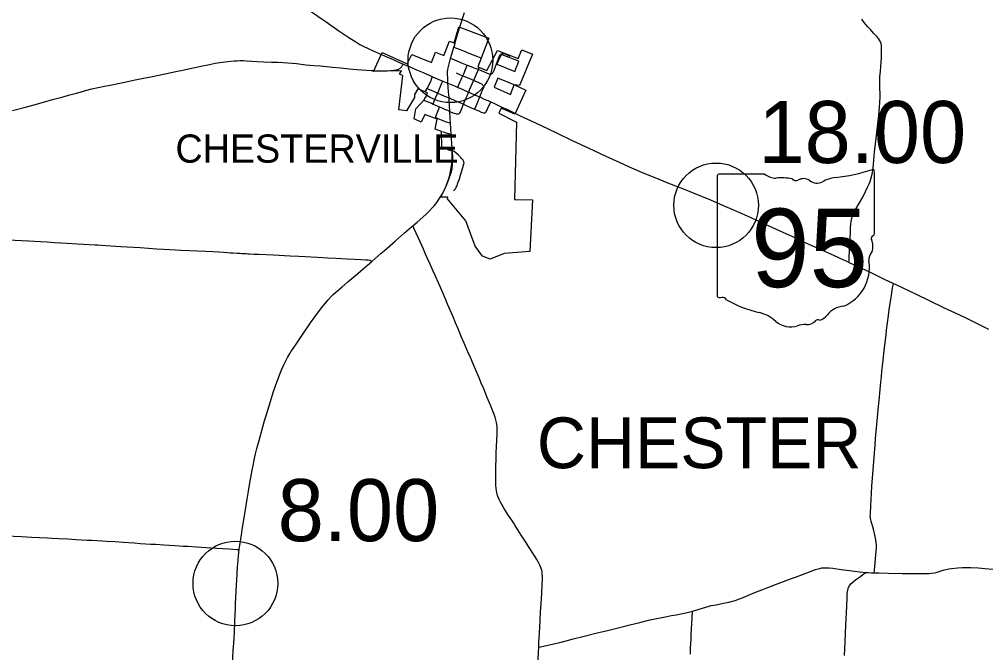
# Model space of a CAD drawing. Extents: x 1813937 to 1948437, y 826606 to 1022856.
# Drawn here: x 1909861 to 1926985, y 893308 to 904541 of the extents above; entities that cross this region are included whole.
import ezdxf

# ---------------------------------------------------------------- set-up
doc = ezdxf.new("R2010")
doc.units = 0
for name, color, linetype in [('Default', 7, 'Continuous'), ('GM_X_City_Street', 7, 'Continuous'), ('GM_X_Corporation', 7, 'Continuous'), ('GM_X_Corporation_Text', 7, 'Continuous'), ('GM_X_County_Road', 7, 'Continuous'), ('GM_X_State_Route', 7, 'Continuous'), ('GM_X_State_Shield', 7, 'Continuous'), ('GM_X_Township_Road', 7, 'Continuous'), ('GM_X_Township_Text', 7, 'Continuous')]:
    doc.layers.add(name, color=color, linetype=linetype)

msp = doc.modelspace()

# ---------------------------------------------------------------- linework, layer by layer
at = {"layer": 'Default'}
for centre in [(1917500, 903814), (1922208, 901242), (1913689, 894536)]:
    msp.add_circle(centre, 750, dxfattribs=at)
at = {"layer": 'GM_X_City_Street'}
for points in [[(1917561, 904044), (1917592, 904033), (1917670, 904005), (1917732, 903981), (1917824, 903943), (1917979, 903882), (1918010, 903871), (1918025, 903864), (1918039, 903855), (1918048, 903847)], [(1917504, 903846), (1917528, 903838), (1917570, 903821), (1917616, 903804), (1917710, 903765), (1917769, 903740), (1917797, 903728)], [(1917996, 903648), (1918029, 903638), (1918075, 903620), (1918151, 903586), (1918166, 903580), (1918182, 903574), (1918198, 903570), (1918214, 903569), (1918230, 903574), (1918243, 903584), (1918254, 903597), (1918261, 903612), (1918293, 903688), (1918318, 903750), (1918359, 903857), (1918371, 903888), (1918379, 903903), (1918388, 903916), (1918401, 903927), (1918416, 903933), (1918432, 903936), (1918449, 903934), (1918465, 903929), (1918495, 903916), (1918554, 903886)], [(1916149, 903631), (1916248, 903628), (1916348, 903629), (1916431, 903632), (1916496, 903637), (1916529, 903641), (1916545, 903643), (1916560, 903648), (1916575, 903653), (1916584, 903657), (1916591, 903661), (1916601, 903667), (1916612, 903676), (1916623, 903686), (1916632, 903696), (1916641, 903708), (1916648, 903721), (1916664, 903747)], [(1917720, 903539), (1917736, 903574), (1917767, 903648), (1917789, 903708), (1917797, 903728)], [(1917797, 903728), (1917830, 903715), (1917905, 903685), (1917965, 903660), (1917996, 903648)], [(1917914, 903457), (1917937, 903512), (1917975, 903599), (1917996, 903648)], [(1917996, 903648), (1917997, 903650), (1918012, 903687)], [(1917087, 903315), (1917109, 903354), (1917126, 903385), (1917140, 903413), (1917156, 903451), (1917166, 903478), (1917179, 903513), (1917183, 903523)], [(1917277, 903231), (1917305, 903305), (1917354, 903423), (1917364, 903446)], [(1917599, 903589), (1917660, 903564), (1917720, 903539)], [(1917631, 903333), (1917646, 903368), (1917703, 903501), (1917720, 903539)], [(1917720, 903539), (1917750, 903527), (1917855, 903483), (1917914, 903457)], [(1917824, 903249), (1917839, 903287), (1917910, 903447), (1917914, 903457)], [(1917914, 903457), (1917960, 903436), (1918020, 903409), (1918049, 903395), (1918063, 903386), (1918074, 903375), (1918083, 903362), (1918089, 903348), (1918091, 903337)], [(1917053, 903257), (1917087, 903315)], [(1917087, 903315), (1917113, 903303), (1917157, 903282), (1917277, 903231)], [(1918019, 903163), (1918065, 903275), (1918085, 903319), (1918091, 903337)], [(1917029, 903107), (1917032, 903105), (1917037, 903102), (1917044, 903099), (1917071, 903089), (1917162, 903052), (1917195, 903038)], [(1917195, 903038), (1917214, 903087), (1917262, 903199), (1917277, 903231)], [(1917277, 903231), (1917397, 903180), (1917475, 903146)], [(1917475, 903146), (1917590, 903095), (1917694, 903051), (1917731, 903035)], [(1917731, 903035), (1917769, 903125), (1917794, 903182), (1917816, 903230), (1917824, 903249)], [(1917929, 902945), (1917937, 902963), (1917955, 903006), (1917973, 903049), (1918016, 903156), (1918019, 903163)], [(1917195, 903038), (1917248, 903013), (1917305, 902988)], [(1917240, 902798), (1917239, 902802), (1917239, 902806), (1917240, 902811), (1917241, 902816), (1917282, 902922), (1917293, 902953), (1917305, 902988)], [(1917305, 902988), (1917334, 902976), (1917384, 902955), (1917426, 902938), (1917446, 902931), (1917461, 902925), (1917474, 902918), (1917490, 902905)], [(1917635, 902863), (1917643, 902866), (1917654, 902872), (1917665, 902882), (1917678, 902900), (1917690, 902931), (1917703, 902961), (1917731, 903035)], [(1917731, 903035), (1917766, 903018), (1917869, 902971), (1917929, 902945)], [(1917929, 902945), (1917956, 902933), (1918001, 902915), (1918046, 902896), (1918088, 902880), (1918094, 902880)], [(1918094, 902880), (1918111, 902883), (1918125, 902892), (1918135, 902904), (1918150, 902934), (1918170, 902980), (1918190, 903026), (1918204, 903053), (1918215, 903076)], [(1917240, 902798), (1917278, 902782), (1917338, 902757), (1917408, 902730), (1917463, 902712), (1917502, 902702)], [(1917490, 902905), (1917512, 902896), (1917559, 902879), (1917587, 902870), (1917602, 902866), (1917618, 902863), (1917626, 902862), (1917635, 902863)], [(1917359, 902551), (1917406, 902536), (1917424, 902530), (1917482, 902512), (1917516, 902502)], [(1917557, 901496), (1917587, 901533), (1917596, 901547), (1917604, 901561), (1917617, 901590), (1917628, 901621), (1917661, 901713), (1917681, 901774), (1917721, 901914), (1917738, 901977), (1917741, 901997), (1917739, 902011), (1917733, 902028), (1917725, 902042), (1917711, 902058), (1917698, 902075), (1917683, 902091), (1917661, 902115), (1917636, 902136), (1917599, 902168), (1917564, 902196), (1917555, 902202), (1917548, 902203), (1917533, 902203)]]:
    msp.add_lwpolyline(points, dxfattribs=at)
at = {"layer": 'GM_X_Corporation'}
for points in [[(1916721, 902918), (1916584, 902938), (1916654, 903543), (1916599, 903568), (1916631, 903626), (1916135, 903615), (1916288, 903951), (1916735, 903752), (1916814, 903917), (1917165, 903776), (1917235, 903959), (1917385, 903901), (1917482, 904153), (1917566, 904121), (1917650, 904410), (1918182, 904204), (1917985, 903695), (1918143, 903631), (1918332, 903987), (1918701, 903844), (1918764, 903997), (1918954, 903920), (1918724, 903365), (1918634, 903376), (1918838, 903282), (1918643, 902861), (1918401, 902967), (1918357, 902876), (1918671, 902719), (1918636, 901348), (1918654, 901348), (1918954, 901337), (1918907, 900420), (1918605, 900399), (1918453, 900386), (1918207, 900289), (1918069, 900338), (1917940, 900518), (1917772, 900966), (1917448, 901359), (1917457, 901388), (1917327, 901389), (1917348, 901423), (1917399, 901529), (1917464, 901686), (1917491, 901757), (1917517, 901838), (1917529, 901891), (1917543, 902040), (1917535, 902243), (1917506, 902241), (1917503, 902207), (1917349, 902273), (1917342, 902550), (1917230, 902590), (1917265, 902771), (1917048, 902854), (1916983, 902716), (1916860, 902776), (1916885, 902954), (1917033, 903113), (1917037, 903116), (1917058, 903162), (1917067, 903157), (1917096, 903235), (1916923, 903308), (1916866, 903208), (1916861, 903155)], [(1918324, 903745), (1918639, 903615), (1918714, 903796), (1918399, 903917)], [(1918276, 903338), (1918562, 903209), (1918627, 903378), (1918342, 903496)]]:
    msp.add_lwpolyline(points, close=True, dxfattribs=at)
at = {"layer": 'GM_X_County_Road'}
for points in [[(1912731, 903635), (1912752, 903640), (1913105, 903715), (1913233, 903742), (1913330, 903762), (1913411, 903775), (1913508, 903789), (1913606, 903799), (1913665, 903803)], [(1913665, 903803), (1913721, 903807), (1913770, 903809), (1913836, 903808), (1913881, 903807), (1913982, 903801), (1914073, 903794), (1914196, 903787), (1914332, 903781), (1914442, 903778), (1914539, 903775), (1914616, 903770), (1914695, 903763), (1914774, 903755), (1914855, 903744), (1914936, 903736), (1915082, 903723), (1915197, 903713), (1915409, 903693), (1915556, 903679), (1915703, 903665), (1915833, 903653), (1916013, 903641), (1916095, 903634), (1916149, 903631)], [(1909738, 902923), (1909944, 902978), (1910102, 903020), (1910292, 903073), (1910450, 903116), (1910640, 903168), (1910735, 903194), (1910877, 903233), (1910940, 903251), (1911035, 903277), (1911147, 903305), (1911259, 903330), (1911371, 903353), (1911500, 903379), (1911757, 903433), (1911885, 903459), (1912062, 903495), (1912223, 903528), (1912528, 903592), (1912656, 903620), (1912731, 903635)], [(1925011, 894725), (1925015, 894769), (1925026, 894899), (1925033, 894980), (1925045, 895111), (1925049, 895176), (1925049, 895225), (1925047, 895258), (1925040, 895307), (1925026, 895371), (1924994, 895498), (1924957, 895641), (1924946, 895688), (1924943, 895705), (1924940, 895737), (1924941, 895770), (1924950, 895917), (1924962, 896129), (1924970, 896259), (1924992, 896553), (1925002, 896700), (1925026, 896994), (1925035, 897109), (1925054, 897353), (1925079, 897614), (1925089, 897728), (1925101, 897842), (1925108, 897908), (1925127, 898103), (1925137, 898201), (1925147, 898299), (1925157, 898396), (1925168, 898494), (1925193, 898722), (1925202, 898803), (1925219, 898949), (1925230, 899030), (1925264, 899290), (1925277, 899388), (1925291, 899501), (1925313, 899647), (1925335, 899776), (1925343, 899825), (1925350, 899857)], [(1909620, 895383), (1909899, 895368), (1910079, 895359), (1910358, 895345), (1910439, 895341), (1910554, 895335), (1910718, 895326), (1910865, 895317), (1911062, 895306), (1911144, 895301), (1911242, 895295), (1911405, 895285), (1911552, 895278), (1911699, 895268), (1911896, 895256), (1912010, 895247), (1912190, 895235), (1912272, 895230), (1912419, 895221), (1912518, 895214), (1912616, 895208), (1912763, 895200), (1912845, 895196), (1913009, 895186), (1913254, 895170), (1913467, 895155), (1913581, 895147), (1913713, 895139), (1913758, 895138)], [(1921788, 894045), (1921909, 894079), (1922082, 894132), (1922120, 894142), (1922167, 894151), (1922210, 894159), (1922339, 894185), (1922436, 894205), (1922499, 894221), (1922546, 894235), (1922624, 894262), (1922685, 894285), (1922867, 894361), (1922973, 894405), (1923064, 894440), (1923125, 894464), (1923263, 894516), (1923356, 894551), (1923524, 894615), (1923616, 894650), (1923739, 894696), (1923893, 894753), (1923970, 894781), (1924017, 894796), (1924048, 894804), (1924081, 894810), (1924113, 894813), (1924163, 894815), (1924212, 894812), (1924277, 894805), (1924423, 894784), (1924570, 894765), (1924749, 894744), (1924863, 894733)], [(1924863, 894733), (1924904, 894730), (1924962, 894727), (1925011, 894725)], [(1925011, 894725), (1925093, 894722), (1925257, 894718), (1925503, 894713), (1925601, 894714), (1925831, 894710), (1925929, 894710), (1925979, 894713), (1926027, 894718), (1926076, 894727), (1926124, 894738), (1926250, 894775), (1926282, 894783), (1926330, 894793), (1926378, 894800), (1926493, 894812), (1926575, 894818), (1926657, 894820), (1926722, 894818), (1926853, 894812), (1926968, 894804), (1927115, 894792)], [(1919066, 893408), (1919150, 893423), (1919278, 893452), (1919310, 893460), (1919358, 893471), (1919438, 893491), (1919549, 893519), (1919613, 893536), (1919677, 893552), (1919868, 893601), (1920075, 893654), (1920282, 893704), (1920426, 893739), (1920681, 893801), (1920857, 893844), (1921009, 893882), (1921129, 893906), (1921306, 893944), (1921419, 893967), (1921500, 893980), (1921613, 894003), (1921674, 894017), (1921788, 894045)], [(1919051, 893107), (1919054, 893152), (1919057, 893206), (1919066, 893408)]]:
    msp.add_lwpolyline(points, dxfattribs=at)
at = {"layer": 'GM_X_State_Route'}
for points in [[(1910495, 907783), (1910557, 907740), (1910747, 907611), (1911086, 907380), (1911330, 907214), (1911560, 907057), (1911873, 906846), (1912198, 906624), (1912442, 906458), (1912700, 906282), (1912890, 906153), (1913214, 905930), (1913444, 905772), (1913742, 905568), (1913903, 905456), (1914417, 905102), (1914809, 904833), (1915246, 904533)], [(1917667, 904406), (1917748, 904663)], [(1915246, 904533), (1915296, 904498), (1915524, 904339), (1915701, 904219), (1915824, 904139), (1915894, 904096), (1915952, 904065), (1916040, 904021), (1916144, 903974), (1916276, 903917)], [(1917457, 903408), (1917452, 903498), (1917450, 903564), (1917451, 903614), (1917454, 903647), (1917459, 903680), (1917471, 903728), (1917497, 903823), (1917504, 903846), (1917561, 904044), (1917570, 904077), (1917582, 904116), (1917602, 904187), (1917638, 904312), (1917667, 904406)], [(1916276, 903917), (1916395, 903866), (1916430, 903850)], [(1916430, 903850), (1916532, 903804), (1916664, 903747), (1916726, 903720), (1916896, 903647), (1917016, 903595), (1917136, 903543), (1917183, 903523), (1917256, 903491), (1917364, 903446), (1917457, 903408)], [(1917457, 903408), (1917570, 903359), (1917631, 903333), (1917668, 903317), (1917811, 903255), (1917824, 903249), (1917941, 903198), (1918019, 903163), (1918100, 903127), (1918190, 903088), (1918215, 903076), (1918293, 903040), (1918413, 902985), (1918511, 902939), (1918651, 902872)], [(1917471, 903214), (1917468, 903246), (1917462, 903343), (1917457, 903408)], [(1917531, 902242), (1917526, 902339), (1917516, 902502), (1917509, 902601), (1917502, 902702), (1917497, 902778), (1917490, 902905), (1917486, 903004), (1917477, 903133), (1917475, 903146), (1917471, 903214)], [(1918651, 902872), (1918738, 902831), (1918798, 902802), (1918932, 902738), (1919110, 902655), (1919380, 902525)], [(1919380, 902525), (1919672, 902386), (1919938, 902259), (1920251, 902114), (1920490, 902006), (1920670, 901926), (1920926, 901815), (1921092, 901746), (1921367, 901637), (1921535, 901570), (1921702, 901503), (1921802, 901464)], [(1917324, 901392), (1917352, 901441), (1917383, 901499), (1917411, 901559), (1917442, 901635), (1917464, 901697), (1917487, 901776), (1917503, 901841), (1917515, 901906), (1917524, 901971), (1917529, 902037), (1917533, 902152), (1917533, 902203), (1917531, 902242)], [(1916835, 900879), (1916911, 900944), (1917011, 901029), (1917071, 901084), (1917129, 901142), (1917185, 901202), (1917217, 901239), (1917257, 901291), (1917303, 901359), (1917324, 901392)], [(1921802, 901464), (1921961, 901401), (1922068, 901357), (1922324, 901247), (1922488, 901173), (1922758, 901053), (1923011, 900937), (1923340, 900789), (1923549, 900694), (1923758, 900597), (1923967, 900502), (1924236, 900381), (1924363, 900323)], [(1913637, 893111), (1913651, 893349), (1913665, 893549), (1913673, 893680), (1913681, 893860), (1913687, 893991), (1913690, 894090), (1913692, 894172), (1913697, 894286), (1913703, 894385), (1913710, 894516), (1913714, 894581), (1913721, 894712), (1913728, 894826), (1913737, 894941), (1913745, 895023), (1913758, 895138), (1913774, 895250), (1913796, 895396), (1913816, 895526), (1913854, 895769), (1913897, 896028), (1913921, 896174), (1913947, 896319), (1913976, 896481), (1913988, 896545), (1914002, 896626), (1914028, 896754), (1914046, 896834), (1914070, 896930), (1914108, 897072), (1914202, 897404), (1914262, 897608), (1914310, 897765), (1914361, 897921), (1914409, 898061), (1914437, 898138), (1914476, 898246), (1914513, 898337), (1914546, 898412), (1914582, 898486), (1914613, 898544), (1914646, 898601), (1914673, 898642), (1914757, 898764), (1914885, 898954), (1915023, 899158), (1915100, 899265), (1915218, 899422), (1915278, 899500), (1915331, 899563), (1915387, 899623), (1915422, 899658), (1915471, 899702), (1915583, 899799), (1915683, 899883), (1915858, 900031), (1915908, 900074), (1916033, 900180), (1916106, 900243), (1916107, 900245), (1916268, 900385), (1916329, 900440), (1916526, 900612), (1916688, 900751), (1916811, 900859), (1916835, 900879)], [(1924363, 900323), (1924400, 900306), (1924560, 900233), (1924579, 900224), (1924772, 900134), (1924935, 900056), (1925186, 899935), (1925350, 899857), (1925393, 899837), (1925763, 899659), (1925970, 899560), (1926251, 899426), (1926444, 899335), (1926622, 899250), (1926872, 899129), (1927033, 899047)]]:
    msp.add_lwpolyline(points, dxfattribs=at)
at = {"layer": 'GM_X_State_Shield'}
for p, q in [((1922228, 901756), (1922228, 899642)), ((1923071, 901792), (1922255, 901792)), ((1925012, 900739), (1925012, 901844)), ((1925012, 900739), (1925012, 900739))]:
    msp.add_line(p, q, dxfattribs=at)
for centre, radius, start, end in [((1922260, 901760), 32.3, 98.1301, 188.1301), ((1923265, 902037), 313, 231.6195, 271.1119), ((1923368, 900606), 1123, 80.4867, 94.9883), ((1924397, 901147), 594, 97.3462, 120.7689), ((1924020, 904673), 2953, 275.8445, 288.9065), ((1924981, 901849), 31, 351.8621, 97.738), ((1923623, 901771), 90.3, 219.7921, 297.1024), ((1923756, 901527), 188, 54.4667, 119.1411), ((1923998, 901862), 226, 233.8562, 294.8282), ((1925005, 900658), 48, 107.944, 210.337), ((1924979, 900735), 33.2, 289.6038, 7.7341), ((1924700, 900518), 288, 340.033, 23.6496), ((1925123, 900276), 210, 136.8065, 186.9296), ((1924186, 900136), 739, 292.3089, 8.9858), ((1922260, 899638), 32.5, 171.9584, 258.3066), ((1922265, 899854), 248, 267.339, 280.6039), ((1922316, 899520), 89.5, 29.7484, 93.2717), ((1923446, 901419), 2132, 240.4129, 257.1985), ((1922811, 898693), 667, 47.1842, 75.836), ((1924497, 899049), 404, 94.4031, 142.5768), ((1923532, 899510), 423, 230.7004, 286.2918), ((1923808, 899352), 226, 268.777, 315.5493), ((1924012, 899147), 63.5, 65.7517, 132.6484), ((1923985, 899438), 239, 282.8732, 323.2771), ((1923777, 898779), 348, 85.6951, 111.2099)]:
    msp.add_arc(centre, radius, start, end, dxfattribs=at)
at = {"layer": 'GM_X_Township_Road'}
for points in [[(1924560, 900233), (1924564, 900270), (1924567, 900302), (1924574, 900450), (1924587, 900761), (1924591, 900843), (1924597, 900909), (1924603, 900957), (1924613, 901006), (1924621, 901037), (1924632, 901068), (1924651, 901113), (1924674, 901157), (1924747, 901285), (1924812, 901400), (1924858, 901487), (1924893, 901561), (1924918, 901621), (1924935, 901667), (1924955, 901730), (1924971, 901794), (1924985, 901858), (1924993, 901906), (1924999, 901972), (1925017, 902184), (1925031, 902331), (1925054, 902527), (1925082, 902738), (1925091, 902836), (1925102, 902983), (1925109, 903065), (1925114, 903163), (1925115, 903229), (1925112, 903310), (1925109, 903392), (1925109, 903458), (1925112, 903523), (1925121, 903621), (1925128, 903703), (1925134, 903785), (1925136, 903850), (1925138, 904047), (1925136, 904080), (1925133, 904096), (1925130, 904112), (1925125, 904128), (1925119, 904143), (1925112, 904158), (1925104, 904172), (1925085, 904199), (1925053, 904236), (1924998, 904297), (1924942, 904357), (1924899, 904406), (1924856, 904455), (1924816, 904506), (1924788, 904546)], [(1919066, 893408), (1919069, 893493), (1919073, 893574), (1919083, 893754), (1919091, 893885), (1919099, 894032), (1919108, 894179), (1919118, 894359), (1919126, 894523), (1919130, 894605), (1919130, 894654), (1919128, 894704), (1919125, 894737), (1919118, 894769), (1919109, 894801), (1919098, 894832), (1919085, 894862), (1919062, 894907), (1919030, 894963), (1918996, 895018), (1918961, 895071), (1918916, 895139), (1918881, 895193), (1918846, 895249), (1918812, 895304), (1918753, 895391), (1918697, 895487), (1918647, 895566), (1918621, 895607), (1918586, 895661), (1918532, 895743), (1918460, 895853), (1918409, 895937), (1918385, 895980), (1918364, 896024), (1918345, 896069), (1918329, 896115), (1918321, 896146), (1918315, 896178), (1918308, 896226), (1918304, 896275), (1918302, 896324), (1918303, 896439), (1918306, 896619), (1918310, 896733), (1918313, 896848), (1918317, 896962), (1918323, 897077), (1918327, 897192), (1918329, 897273), (1918328, 897323), (1918325, 897356), (1918319, 897388), (1918307, 897436), (1918293, 897484), (1918277, 897530), (1918253, 897591), (1918209, 897697), (1918146, 897848), (1918121, 897909), (1918078, 898015), (1918059, 898060), (1918009, 898181), (1917930, 898360), (1917853, 898541), (1917807, 898646), (1917741, 898796), (1917691, 898917), (1917636, 899054), (1917591, 899159), (1917546, 899265), (1917450, 899491), (1917418, 899567), (1917353, 899717), (1917287, 899867), (1917233, 899986), (1917193, 900076), (1917134, 900211), (1917093, 900300), (1917060, 900375), (1917020, 900465), (1916933, 900659), (1916892, 900748), (1916853, 900838), (1916835, 900879)], [(1909664, 900631), (1910025, 900611), (1910237, 900599), (1910352, 900592), (1910483, 900584), (1910706, 900572), (1910893, 900561), (1911203, 900544), (1911251, 900539), (1911316, 900534), (1911480, 900524), (1911660, 900514), (1912004, 900492), (1912152, 900482), (1912299, 900473), (1912413, 900465), (1912528, 900459), (1912626, 900453), (1912724, 900447), (1912880, 900442), (1913021, 900435), (1913163, 900428), (1913292, 900421), (1913398, 900415), (1913476, 900410), (1913548, 900406), (1913604, 900401), (1913650, 900398), (1913720, 900395), (1913770, 900392), (1913803, 900390), (1913843, 900387), (1913879, 900386), (1913908, 900384), (1913934, 900383), (1914021, 900378), (1914102, 900375), (1914366, 900362), (1914661, 900348), (1914811, 900339), (1914927, 900332), (1915147, 900320), (1915329, 900312), (1915471, 900304), (1915572, 900299), (1915673, 900294), (1915801, 900286), (1915919, 900279), (1915993, 900276), (1916044, 900273), (1916069, 900268), (1916082, 900264), (1916091, 900256), (1916106, 900243)], [(1924480, 893258), (1924492, 893503), (1924499, 893651), (1924507, 893798), (1924513, 893913), (1924517, 894011), (1924529, 894273), (1924532, 894355), (1924535, 894388), (1924541, 894420), (1924545, 894436), (1924550, 894452), (1924556, 894467), (1924563, 894481), (1924572, 894495), (1924581, 894509), (1924603, 894533), (1924639, 894567), (1924677, 894598), (1924770, 894666), (1924809, 894695), (1924863, 894733)], [(1921752, 893279), (1921757, 893395), (1921763, 893540), (1921768, 893628), (1921774, 893731), (1921783, 893919), (1921788, 894045)]]:
    msp.add_lwpolyline(points, dxfattribs=at)

# ---------------------------------------------------------------- texts
at = {"layer": 'Default'}
for s, p in [('18.00', (1922958, 901992)), ('8.00', (1914439, 895286))]:
    msp.add_text(s, height=1100, dxfattribs=at).set_placement(p)
at = {"layer": 'GM_X_Corporation_Text'}
msp.add_text('CHESTERVILLE', height=500, rotation=0, dxfattribs=at).set_placement((1912627, 901998))
at = {"layer": 'GM_X_State_Shield'}
msp.add_text('95', height=1392.2, dxfattribs=at).set_placement((1922828, 899791))
at = {"layer": 'GM_X_Township_Text'}
msp.add_text('CHESTER', height=900, rotation=0, dxfattribs=at).set_placement((1919032, 896580))

doc.saveas('drawing.dxf')
